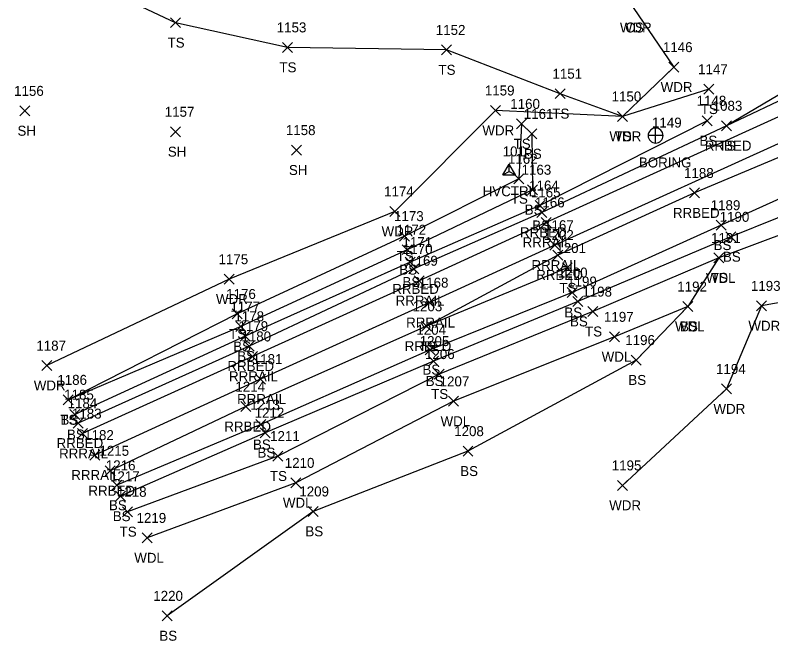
# Model space of a CAD drawing. Extents: x 1640777 to 1641692, y 610911 to 611377.
# Drawn here: x 1641267.9 to 1641419.5, y 611128.6 to 611254.1 of the extents above; entities that cross this region are included whole.
import ezdxf

# ---------------------------------------------------------------- set-up
doc = ezdxf.new("R2010")
doc.units = 0
for name, color, linetype in [('C_A', 7, 'Continuous'), ('C_I', 7, 'Continuous'), ('CPSM', 7, 'Continuous'), ('G_A', 7, 'Continuous'), ('G_I', 7, 'Continuous'), ('GA_P', 7, 'Continuous'), ('L_A', 7, 'Continuous'), ('L_I', 7, 'Continuous'), ('L_TIC', 7, 'Continuous'), ('LAWA', 7, 'Continuous'), ('LELB', 7, 'Continuous'), ('R_A', 7, 'Continuous'), ('R_I', 7, 'Continuous'), ('R_TIC', 7, 'Continuous'), ('RR', 7, 'Continuous'), ('RRB', 7, 'Continuous')]:
    doc.layers.add(name, color=color, linetype=linetype)

msp = doc.modelspace()

# ---------------------------------------------------------------- linework, layer by layer
at = {"layer": 'CPSM'}
for p, q in [((1641365.74, 611222.04), (1641366.99, 611224.21)), ((1641368.24, 611222.04), (1641366.99, 611224.21)), ((1641366.99, 611222.76), (1641366.99, 611224.21)), ((1641365.74, 611222.04), (1641366.99, 611222.76)), ((1641365.74, 611222.04), (1641368.24, 611222.04)), ((1641366.99, 611222.76), (1641366.99, 611222.76)), ((1641366.99, 611222.76), (1641368.24, 611222.04))]:
    msp.add_line(p, q, dxfattribs=at)
at = {"layer": 'GA_P'}
for p, q in [((1641396.36, 611229.94), (1641396.36, 611231.44)), ((1641396.36, 611229.94), (1641394.86, 611229.94)), ((1641397.86, 611229.94), (1641396.36, 611229.94)), ((1641396.36, 611228.44), (1641396.36, 611229.94))]:
    msp.add_line(p, q, dxfattribs=at)
for start, end in [(90, 180), (0, 90), (180, 270), (270, 0)]:
    msp.add_arc((1641396.36, 611229.94), 1.5, start, end, dxfattribs=at)
at = {"layer": 'L_TIC'}
for points in [[(1641299.07, 611251.58), (1641301.07, 611253.58)], [(1641301.07, 611251.58), (1641299.07, 611253.58)], [(1641321.5, 611246.63), (1641323.5, 611248.63)], [(1641323.5, 611246.63), (1641321.5, 611248.63)], [(1641353.4, 611246.12), (1641355.4, 611248.12)], [(1641355.4, 611246.12), (1641353.4, 611248.12)], [(1641399.01, 611242.67), (1641401.01, 611244.67)], [(1641401.01, 611242.67), (1641399.01, 611244.67)], [(1641406.01, 611238.25), (1641408.01, 611240.25)], [(1641408.01, 611238.25), (1641406.01, 611240.25)], [(1641376.23, 611237.34), (1641378.23, 611239.34)], [(1641378.23, 611237.34), (1641376.23, 611239.34)], [(1641268.88, 611233.9), (1641270.88, 611235.9)], [(1641270.88, 611233.9), (1641268.88, 611235.9)], [(1641363.25, 611233.98), (1641365.25, 611235.98)], [(1641365.25, 611233.98), (1641363.25, 611235.98)], [(1641388.74, 611232.78), (1641390.74, 611234.78)], [(1641390.74, 611232.78), (1641388.74, 611234.78)], [(1641388.74, 611232.78), (1641390.74, 611234.78)], [(1641390.74, 611232.78), (1641388.74, 611234.78)], [(1641405.71, 611231.91), (1641407.71, 611233.91)], [(1641407.71, 611231.91), (1641405.71, 611233.91)], [(1641368.47, 611231.29), (1641370.47, 611233.29)], [(1641370.47, 611231.29), (1641368.47, 611233.29)], [(1641409.57, 611230.91), (1641411.57, 611232.91)], [(1641411.57, 611230.91), (1641409.57, 611232.91)], [(1641299.05, 611229.71), (1641301.05, 611231.71)], [(1641301.05, 611229.71), (1641299.05, 611231.71)], [(1641370.52, 611229.28), (1641372.52, 611231.28)], [(1641372.52, 611229.28), (1641370.52, 611231.28)], [(1641323.33, 611226.03), (1641325.33, 611228.03)], [(1641325.33, 611226.03), (1641323.33, 611228.03)], [(1641367.91, 611220.27), (1641369.91, 611222.27)], [(1641369.91, 611220.27), (1641367.91, 611222.27)], [(1641370.65, 611218.08), (1641372.65, 611220.08)], [(1641372.65, 611218.08), (1641370.65, 611220.08)], [(1641343.03, 611213.73), (1641345.03, 611215.73)], [(1641345.03, 611213.73), (1641343.03, 611215.73)], [(1641372.17, 611214.91), (1641374.17, 611216.91)], [(1641374.17, 611214.91), (1641372.17, 611216.91)], [(1641408.53, 611210.97), (1641410.53, 611212.97)], [(1641410.53, 611210.97), (1641408.53, 611212.97)], [(1641345.01, 611208.78), (1641347.01, 611210.78)], [(1641347.01, 611208.78), (1641345.01, 611210.78)], [(1641410.42, 611208.64), (1641412.42, 611210.64)], [(1641412.42, 611208.64), (1641410.42, 611210.64)], [(1641345.52, 611206.05), (1641347.52, 611208.05)], [(1641347.52, 611206.05), (1641345.52, 611208.05)], [(1641408.03, 611204.4), (1641410.03, 611206.4)], [(1641410.03, 611204.4), (1641408.03, 611206.4)], [(1641408.03, 611204.4), (1641410.03, 611206.4)], [(1641410.03, 611204.4), (1641408.03, 611206.4)], [(1641346.15, 611203.56), (1641348.15, 611205.56)], [(1641348.15, 611203.56), (1641346.15, 611205.56)], [(1641377.65, 611202.38), (1641379.65, 611204.38)], [(1641379.65, 611202.38), (1641377.65, 611204.38)], [(1641309.82, 611200.14), (1641311.82, 611202.14)], [(1641311.82, 611200.14), (1641309.82, 611202.14)], [(1641378.62, 611197.46), (1641380.62, 611199.46)], [(1641380.62, 611197.46), (1641378.62, 611199.46)], [(1641379.75, 611195.66), (1641381.75, 611197.66)], [(1641381.75, 611195.66), (1641379.75, 611197.66)], [(1641401.82, 611194.65), (1641403.82, 611196.65)], [(1641403.82, 611194.65), (1641401.82, 611196.65)], [(1641401.82, 611194.65), (1641403.82, 611196.65)], [(1641403.82, 611194.65), (1641401.82, 611196.65)], [(1641416.6, 611194.79), (1641418.6, 611196.79)], [(1641418.6, 611194.79), (1641416.6, 611196.79)], [(1641311.41, 611193.16), (1641313.41, 611195.16)], [(1641313.41, 611193.16), (1641311.41, 611195.16)], [(1641382.79, 611193.64), (1641384.79, 611195.64)], [(1641384.79, 611193.64), (1641382.79, 611195.64)], [(1641349.39, 611190.7), (1641351.39, 611192.7)], [(1641351.39, 611190.7), (1641349.39, 611192.7)], [(1641312.2, 611190.62), (1641314.2, 611192.62)], [(1641314.2, 611190.62), (1641312.2, 611192.62)], [(1641313.01, 611188.69), (1641315.01, 611190.69)], [(1641315.01, 611188.69), (1641313.01, 611190.69)], [(1641387.13, 611188.58), (1641389.13, 611190.58)], [(1641389.13, 611188.58), (1641387.13, 611190.58)], [(1641350.15, 611185.99), (1641352.15, 611187.99)], [(1641352.15, 611185.99), (1641350.15, 611187.99)], [(1641350.81, 611183.71), (1641352.81, 611185.71)], [(1641352.81, 611183.71), (1641350.81, 611185.71)], [(1641391.45, 611183.92), (1641393.45, 611185.92)], [(1641393.45, 611183.92), (1641391.45, 611185.92)], [(1641273.29, 611182.81), (1641275.29, 611184.81)], [(1641275.29, 611182.81), (1641273.29, 611184.81)], [(1641351.93, 611181.11), (1641353.93, 611183.11)], [(1641353.93, 611181.11), (1641351.93, 611183.11)], [(1641409.59, 611178.12), (1641411.59, 611180.12)], [(1641411.59, 611178.12), (1641409.59, 611180.12)], [(1641277.55, 611175.94), (1641279.55, 611177.94)], [(1641279.55, 611175.94), (1641277.55, 611177.94)], [(1641277.55, 611175.94), (1641279.55, 611177.94)], [(1641279.55, 611175.94), (1641277.55, 611177.94)], [(1641354.81, 611175.64), (1641356.81, 611177.64)], [(1641356.81, 611175.64), (1641354.81, 611177.64)], [(1641278.86, 611172.97), (1641280.86, 611174.97)], [(1641280.86, 611172.97), (1641278.86, 611174.97)], [(1641316.17, 611170.97), (1641318.17, 611172.97)], [(1641318.17, 611170.97), (1641316.17, 611172.97)], [(1641317.07, 611169.34), (1641319.07, 611171.34)], [(1641319.07, 611169.34), (1641317.07, 611171.34)], [(1641357.73, 611165.65), (1641359.73, 611167.65)], [(1641359.73, 611165.65), (1641357.73, 611167.65)], [(1641319.6, 611164.66), (1641321.6, 611166.66)], [(1641321.6, 611164.66), (1641319.6, 611166.66)], [(1641323.2, 611159.29), (1641325.2, 611161.29)], [(1641325.2, 611159.29), (1641323.2, 611161.29)], [(1641287.28, 611158.79), (1641289.28, 611160.79)], [(1641289.28, 611158.79), (1641287.28, 611160.79)], [(1641388.69, 611158.78), (1641390.69, 611160.78)], [(1641390.69, 611158.78), (1641388.69, 611160.78)], [(1641288.05, 611156.6), (1641290.05, 611158.6)], [(1641290.05, 611156.6), (1641288.05, 611158.6)], [(1641289.45, 611153.49), (1641291.45, 611155.49)], [(1641291.45, 611153.49), (1641289.45, 611155.49)], [(1641326.68, 611153.56), (1641328.68, 611155.56)], [(1641328.68, 611153.56), (1641326.68, 611155.56)], [(1641293.38, 611148.25), (1641295.38, 611150.25)], [(1641295.38, 611148.25), (1641293.38, 611150.25)], [(1641297.39, 611132.62), (1641299.39, 611134.62)], [(1641299.39, 611132.62), (1641297.39, 611134.62)]]:
    msp.add_lwpolyline(points, dxfattribs=at)
at = {"layer": 'LAWA'}
for points in [[(1641285.47, 611287.27), (1641314.23, 611274.82), (1641324.92, 611263.14), (1641353.52, 611262.16), (1641381, 611260.98), (1641391.84, 611255.61), (1641400.01, 611243.67), (1641389.74, 611233.78), (1641364.25, 611234.98), (1641344.03, 611214.73), (1641310.82, 611201.14), (1641274.29, 611183.81)], [(1641483.8, 611238.22), (1641486.73, 611216.43), (1641476.87, 611212.8), (1641466.05, 611213.97), (1641462.11, 611214.6), (1641443.56, 611218.04), (1641431.06, 611213.64), (1641409.03, 611205.4), (1641402.82, 611195.65), (1641388.13, 611189.58), (1641355.81, 611176.64), (1641324.2, 611160.29), (1641294.38, 611149.25)], [(1641473.47, 611200.43), (1641461.6, 611201.43), (1641439.92, 611201.58), (1641433.27, 611198.61), (1641417.6, 611195.79), (1641410.59, 611179.12), (1641389.69, 611159.78)]]:
    msp.add_lwpolyline(points, dxfattribs=at)
at = {"layer": 'LELB'}
for points in [[(1641407.01, 611239.25), (1641389.74, 611233.78), (1641377.23, 611238.34), (1641354.4, 611247.12), (1641322.5, 611247.63), (1641300.07, 611252.58), (1641275.31, 611264.24)], [(1641461.92, 611262.06), (1641449.9, 611255.27), (1641429.67, 611243.2), (1641410.57, 611231.91)], [(1641369.47, 611232.29), (1641368.91, 611221.27), (1641346.01, 611209.78), (1641312.41, 611194.16), (1641278.55, 611176.94)], [(1641406.71, 611232.91), (1641373.17, 611215.91), (1641347.15, 611204.56), (1641314.01, 611189.69), (1641279.86, 611173.97)], [(1641371.52, 611230.28), (1641371.65, 611219.08), (1641346.52, 611207.05), (1641313.2, 611191.62), (1641278.55, 611176.94)], [(1641444.14, 611222.31), (1641428.88, 611220.73), (1641409.53, 611211.97), (1641379.62, 611198.46), (1641351.15, 611186.99), (1641317.17, 611171.97), (1641288.28, 611159.79)], [(1641443.56, 611218.04), (1641430.03, 611217.09), (1641411.42, 611209.64), (1641380.75, 611196.66), (1641351.81, 611184.71), (1641318.07, 611170.34), (1641289.05, 611157.6)], [(1641409.03, 611205.4), (1641383.79, 611194.64), (1641352.93, 611182.11), (1641320.6, 611165.66), (1641290.45, 611154.49)], [(1641378.65, 611203.38), (1641350.39, 611191.7)], [(1641402.82, 611195.65), (1641392.45, 611184.92), (1641358.73, 611166.65), (1641327.68, 611154.56), (1641298.39, 611133.62)]]:
    msp.add_lwpolyline(points, dxfattribs=at)
at = {"layer": 'R_TIC'}
for points in [[(1641409.57, 611230.91), (1641411.57, 611232.91)], [(1641411.57, 611230.91), (1641409.57, 611232.91)], [(1641403.18, 611217.43), (1641405.18, 611219.43)], [(1641405.18, 611217.43), (1641403.18, 611219.43)], [(1641372.51, 611213.53), (1641374.51, 611215.53)], [(1641374.51, 611213.53), (1641372.51, 611215.53)], [(1641373.39, 611211.53), (1641375.39, 611213.53)], [(1641375.39, 611211.53), (1641373.39, 611213.53)], [(1641375.17, 611206.95), (1641377.17, 611208.95)], [(1641377.17, 611206.95), (1641375.17, 611208.95)], [(1641375.76, 611204.98), (1641377.76, 611206.98)], [(1641377.76, 611204.98), (1641375.76, 611206.98)], [(1641346.89, 611202.18), (1641348.89, 611204.18)], [(1641348.89, 611202.18), (1641346.89, 611204.18)], [(1641347.91, 611199.83), (1641349.91, 611201.83)], [(1641349.91, 611199.83), (1641347.91, 611201.83)], [(1641350.03, 611195.44), (1641352.03, 611197.44)], [(1641352.03, 611195.44), (1641350.03, 611197.44)], [(1641349.39, 611190.7), (1641351.39, 611192.7)], [(1641351.39, 611190.7), (1641349.39, 611192.7)], [(1641313.84, 611186.71), (1641315.84, 611188.71)], [(1641315.84, 611186.71), (1641313.84, 611188.71)], [(1641314.51, 611184.65), (1641316.51, 611186.65)], [(1641316.51, 611184.65), (1641314.51, 611186.65)], [(1641316.13, 611180.1), (1641318.13, 611182.1)], [(1641318.13, 611180.1), (1641316.13, 611182.1)], [(1641313.2, 611174.58), (1641315.2, 611176.58)], [(1641315.2, 611174.58), (1641313.2, 611176.58)], [(1641279.56, 611171.25), (1641281.56, 611173.25)], [(1641281.56, 611171.25), (1641279.56, 611173.25)], [(1641280.43, 611169.17), (1641282.43, 611171.17)], [(1641282.43, 611169.17), (1641280.43, 611171.17)], [(1641282.87, 611164.86), (1641284.87, 611166.86)], [(1641284.87, 611164.86), (1641282.87, 611166.86)], [(1641285.94, 611161.71), (1641287.94, 611163.71)], [(1641287.94, 611161.71), (1641285.94, 611163.71)]]:
    msp.add_lwpolyline(points, dxfattribs=at)
at = {"layer": 'RR'}
for points in [[(1641609.96, 611319.36), (1641563.93, 611298), (1641524.67, 611280.09), (1641481.95, 611260.74), (1641425.41, 611235.68), (1641374.39, 611212.53), (1641348.91, 611200.83), (1641315.51, 611185.65), (1641281.43, 611170.17)], [(1641614.1, 611315.75), (1641566.38, 611293.79), (1641526.34, 611275.4), (1641484.31, 611256.48), (1641427.45, 611231.21), (1641376.17, 611207.95), (1641351.03, 611196.44), (1641317.13, 611181.1), (1641283.87, 611165.86)]]:
    msp.add_lwpolyline(points, dxfattribs=at)
at = {"layer": 'RRB'}
for points in [[(1641601.06, 611318.54), (1641562.35, 611300.7), (1641524.48, 611282.6), (1641480.55, 611262.73), (1641424.68, 611238.55), (1641410.57, 611231.91), (1641373.51, 611214.53), (1641347.89, 611203.18), (1641314.84, 611187.71), (1641280.56, 611172.25)], [(1641612.04, 611311.61), (1641567.84, 611291.83), (1641527.22, 611272.95), (1641485.65, 611254.42), (1641428.83, 611228.82), (1641404.18, 611218.43), (1641376.76, 611205.98), (1641350.39, 611191.7), (1641314.2, 611175.58), (1641286.94, 611162.71)]]:
    msp.add_lwpolyline(points, dxfattribs=at)

# ---------------------------------------------------------------- texts
at = {"layer": 'C_A'}
msp.add_text('HVCTRL', height=2, dxfattribs=at).set_placement((1641361.68, 611217.76))
at = {"layer": 'C_I'}
msp.add_text('101', height=2, dxfattribs=at).set_placement((1641365.68, 611225.76))
at = {"layer": 'G_A'}
msp.add_text('BORING', height=2, dxfattribs=at).set_placement((1641393, 611223.54))
at = {"layer": 'G_I'}
msp.add_text('1149', height=2, dxfattribs=at).set_placement((1641395.63, 611231.54))
at = {"layer": 'L_A'}
for s, p in [('WDR', (1641389.2, 611250.61)), ('CS', (1641390.28, 611250.61)), ('TS', (1641298.48, 611247.58)), ('TS', (1641320.91, 611242.63)), ('TS', (1641352.81, 611242.12)), ('WDR', (1641397.37, 611238.67)), ('TS', (1641375.64, 611233.34)), ('TS', (1641405.42, 611234.25)), ('SH', (1641268.37, 611229.9)), ('WDR', (1641361.61, 611229.98)), ('WDR', (1641387.1, 611228.78)), ('TS', (1641388.15, 611228.78)), ('TS', (1641367.88, 611227.29)), ('BS', (1641405.15, 611227.91)), ('SH', (1641298.53, 611225.71)), ('TS', (1641408.98, 611226.91)), ('BS', (1641369.96, 611225.28)), ('SH', (1641322.81, 611222.03)), ('TS', (1641367.32, 611216.27)), ('BS', (1641370.1, 611214.08)), ('BS', (1641371.61, 611210.91)), ('WDR', (1641341.4, 611209.73)), ('BS', (1641407.98, 611206.97)), ('TS', (1641344.42, 611204.78)), ('BS', (1641409.86, 611204.64)), ('BS', (1641344.96, 611202.05)), ('WDL', (1641406.45, 611200.4)), ('TS', (1641407.44, 611200.4)), ('BS', (1641345.59, 611199.56)), ('TS', (1641377.06, 611198.38)), ('WDR', (1641308.19, 611196.14)), ('BS', (1641378.06, 611193.46)), ('BS', (1641379.19, 611191.66)), ('BS', (1641401.26, 611190.65)), ('WDR', (1641414.96, 611190.79)), ('TS', (1641310.82, 611189.16)), ('TS', (1641382.2, 611189.64)), ('WDL', (1641400.24, 611190.65)), ('BS', (1641311.64, 611186.62)), ('TS', (1641348.8, 611186.7)), ('BS', (1641312.45, 611184.69)), ('WDL', (1641385.54, 611184.58)), ('BS', (1641349.59, 611181.99)), ('WDR', (1641271.65, 611178.81)), ('BS', (1641350.25, 611179.71)), ('BS', (1641390.89, 611179.92)), ('TS', (1641351.34, 611177.11)), ('WDR', (1641407.96, 611174.12)), ('TS', (1641276.96, 611171.94)), ('BS', (1641276.99, 611171.94)), ('WDL', (1641353.23, 611171.64)), ('BS', (1641278.3, 611168.97)), ('BS', (1641315.61, 611166.97)), ('BS', (1641316.51, 611165.34)), ('TS', (1641319.01, 611160.66)), ('BS', (1641357.17, 611161.65)), ('BS', (1641286.72, 611154.79)), ('WDL', (1641321.61, 611155.29)), ('WDR', (1641387.05, 611154.78)), ('BS', (1641287.49, 611152.6)), ('TS', (1641288.86, 611149.49)), ('BS', (1641326.12, 611149.56)), ('WDL', (1641291.8, 611144.25)), ('BS', (1641296.83, 611128.62))]:
    msp.add_text(s, height=2, dxfattribs=at).set_placement(p)
at = {"layer": 'L_I'}
for s, p in [('1153', (1641320.37, 611250.63)), ('1152', (1641352.27, 611250.12)), ('1146', (1641397.82, 611246.67)), ('1147', (1641404.88, 611242.25)), ('1151', (1641375.67, 611241.34)), ('1156', (1641267.7, 611237.9)), ('1159', (1641362.11, 611237.98)), ('1150', (1641387.53, 611236.78)), ('1150', (1641387.53, 611236.78)), ('1160', (1641367.21, 611235.29)), ('1148', (1641404.58, 611235.91)), ('1083', (1641407.8, 611234.91)), ('1157', (1641297.92, 611233.71)), ('1161', (1641369.91, 611233.28)), ('1158', (1641322.2, 611230.03)), ('1162', (1641366.74, 611224.27)), ('1163', (1641369.48, 611222.08)), ('1164', (1641371, 611218.91)), ('1174', (1641341.91, 611217.73)), ('1189', (1641407.4, 611214.97)), ('1173', (1641343.89, 611212.78)), ('1190', (1641409.2, 611212.64)), ('1172', (1641344.39, 611210.05)), ('1171', (1641345.59, 611207.56)), ('1191', (1641407.48, 611208.4)), ('1191', (1641407.48, 611208.4)), ('1201', (1641376.44, 611206.38)), ('1175', (1641308.7, 611204.14)), ('1200', (1641376.76, 611201.46)), ('1199', (1641378.62, 611199.66)), ('1192', (1641400.7, 611198.65)), ('1192', (1641400.7, 611198.65)), ('1193', (1641415.47, 611198.79)), ('1176', (1641310.23, 611197.16)), ('1198', (1641381.66, 611197.64)), ('1177', (1641311.07, 611194.62)), ('1203', (1641347.62, 611194.7)), ('1178', (1641311.88, 611192.69)), ('1197', (1641386, 611192.58)), ('1204', (1641348.38, 611189.99)), ('1205', (1641349.04, 611187.71)), ('1196', (1641390.27, 611187.92)), ('1187', (1641272.16, 611186.81)), ('1206', (1641350.11, 611185.11)), ('1194', (1641408.47, 611182.12)), ('1186', (1641276.37, 611179.94)), ('1186', (1641276.37, 611179.94)), ('1207', (1641353.04, 611179.64)), ('1185', (1641277.74, 611176.97)), ('1213', (1641315.05, 611174.97)), ('1212', (1641315.94, 611173.34)), ('1208', (1641355.96, 611169.65)), ('1211', (1641319.04, 611168.66)), ('1216', (1641286.1, 611162.79)), ('1210', (1641321.98, 611163.29)), ('1195', (1641387.56, 611162.78)), ('1217', (1641286.93, 611160.6)), ('1218', (1641288.32, 611157.49)), ('1209', (1641324.9, 611157.56)), ('1219', (1641292.25, 611152.25)), ('1220', (1641295.61, 611136.62))]:
    msp.add_text(s, height=2, dxfattribs=at).set_placement(p)
at = {"layer": 'R_A'}
for s, p in [('RRBED', (1641406.22, 611226.91)), ('RRBED', (1641399.83, 611213.43)), ('RRBED', (1641369.16, 611209.53)), ('RRRAIL', (1641369.68, 611207.53)), ('RRRAIL', (1641371.46, 611202.95)), ('RRBED', (1641372.41, 611200.98)), ('RRBED', (1641343.53, 611198.18)), ('RRRAIL', (1641344.21, 611195.83)), ('RRRAIL', (1641346.32, 611191.44)), ('RRBED', (1641346.03, 611186.7)), ('RRBED', (1641310.48, 611182.71)), ('RRRAIL', (1641310.8, 611180.65)), ('RRRAIL', (1641312.42, 611176.1)), ('RRBED', (1641309.85, 611170.58)), ('RRBED', (1641276.21, 611167.25)), ('RRRAIL', (1641276.72, 611165.17)), ('RRRAIL', (1641279.16, 611160.86)), ('RRBED', (1641282.59, 611157.71))]:
    msp.add_text(s, height=2, dxfattribs=at).set_placement(p)
at = {"layer": 'R_I'}
for s, p in [('1083', (1641407.8, 611234.91)), ('1188', (1641402.06, 611221.43)), ('1165', (1641371.34, 611217.53)), ('1166', (1641372.16, 611215.53)), ('1167', (1641373.99, 611210.95)), ('1202', (1641373.99, 611208.98)), ('1170', (1641345.67, 611206.18)), ('1169', (1641346.73, 611203.83)), ('1168', (1641348.86, 611199.44)), ('1203', (1641347.62, 611194.7)), ('1179', (1641312.7, 611190.71)), ('1180', (1641313.29, 611188.65)), ('1181', (1641315.57, 611184.1)), ('1214', (1641312.08, 611178.58)), ('1184', (1641278.43, 611175.25)), ('1183', (1641279.3, 611173.17)), ('1182', (1641281.75, 611168.86)), ('1215', (1641284.81, 611165.71))]:
    msp.add_text(s, height=2, dxfattribs=at).set_placement(p)

doc.saveas('drawing.dxf')
